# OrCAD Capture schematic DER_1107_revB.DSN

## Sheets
1 PAGE2: size B
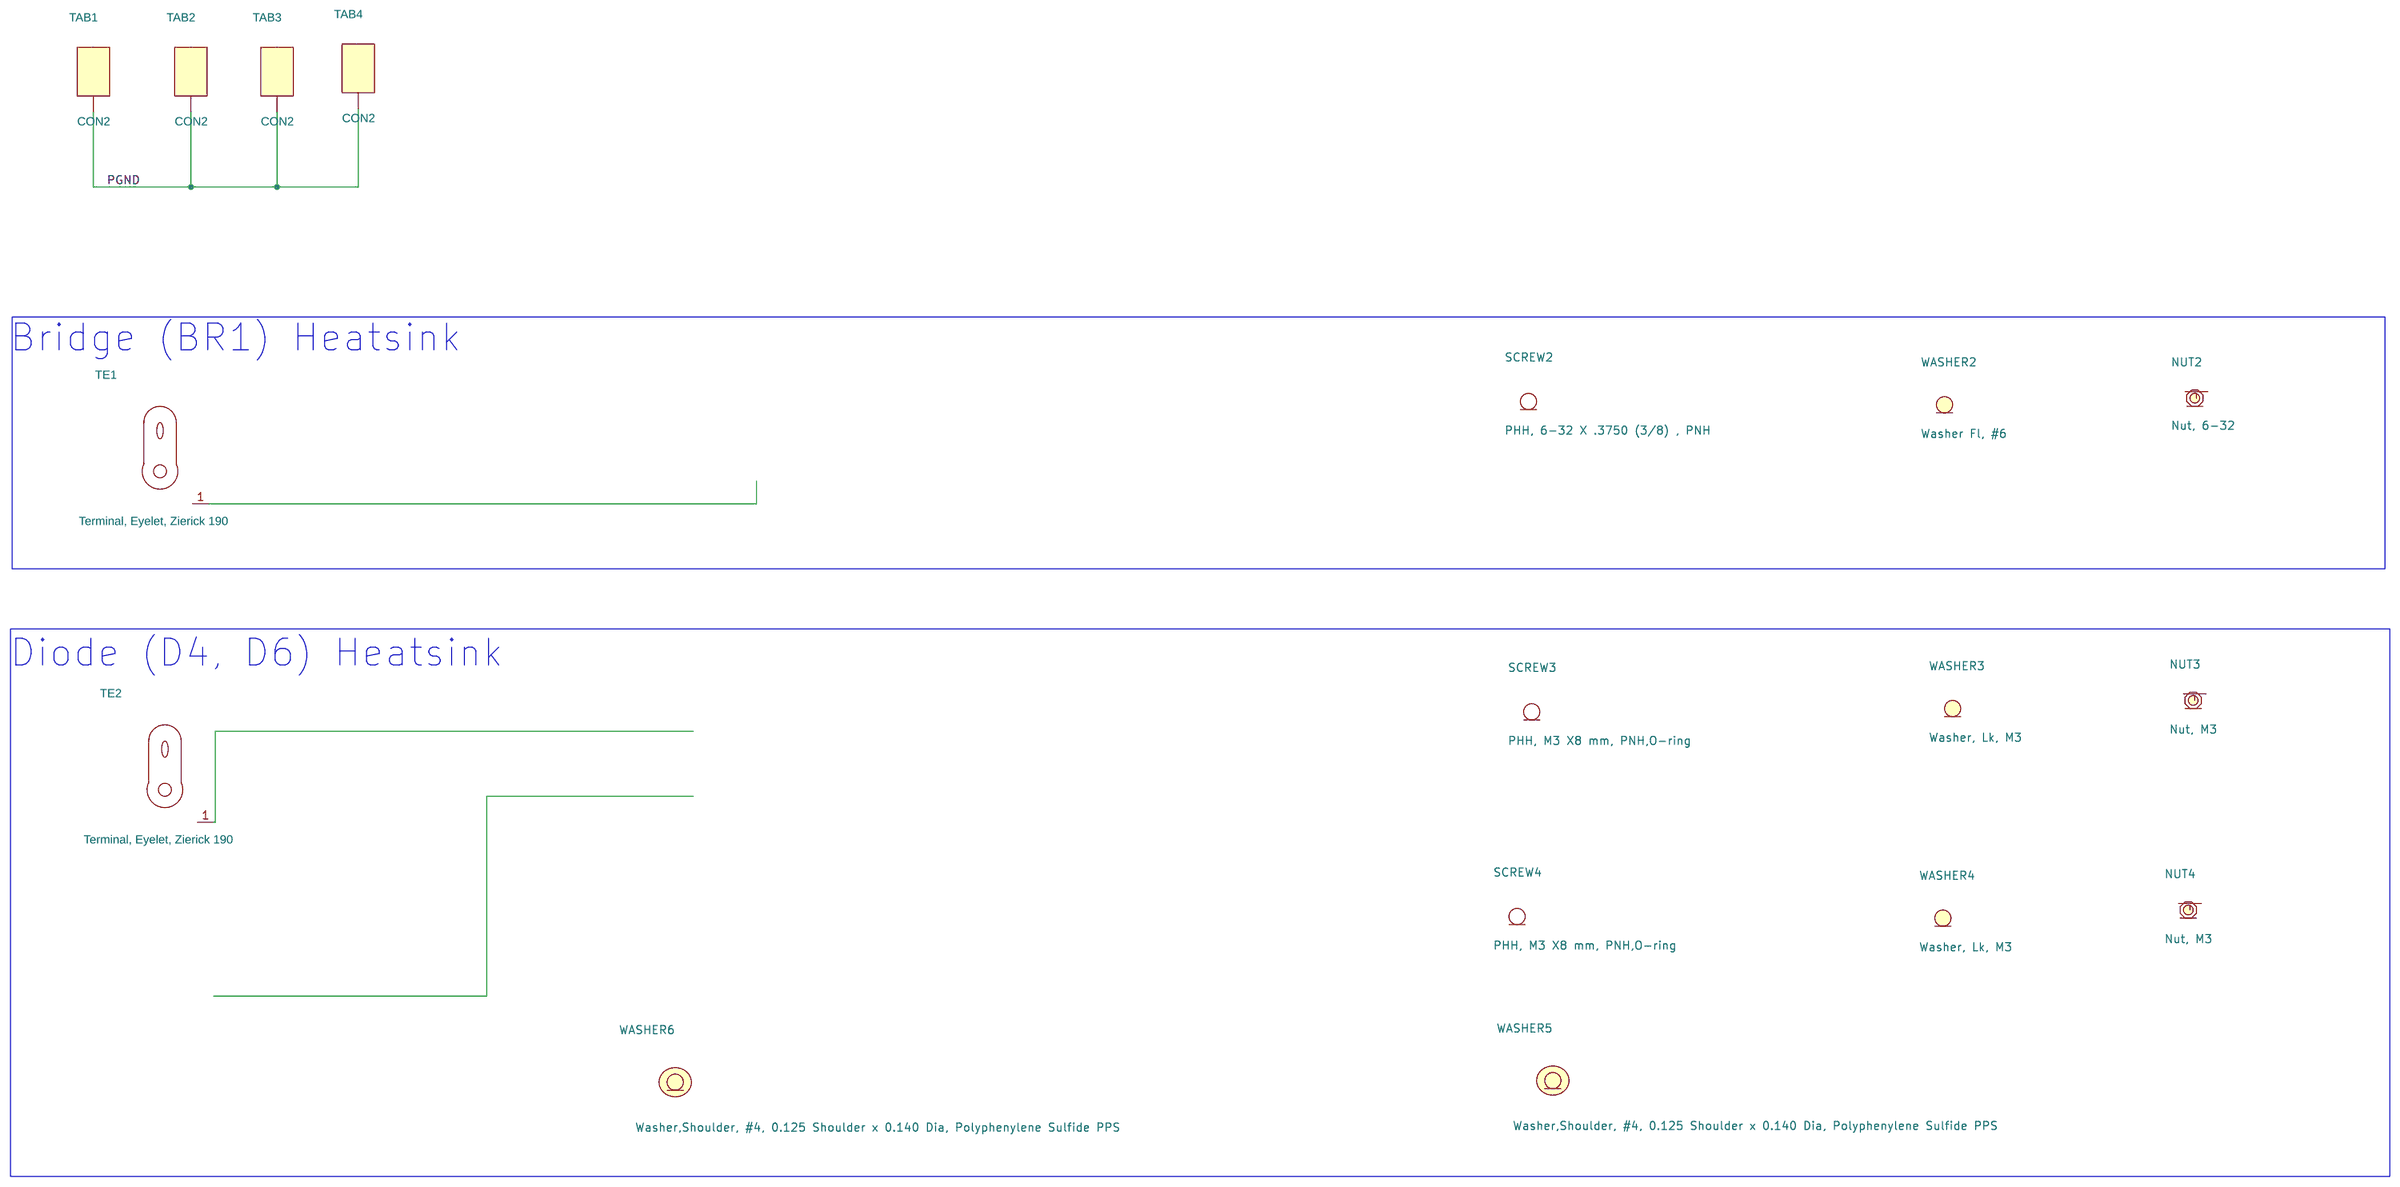
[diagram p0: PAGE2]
2 PAGE1: size C
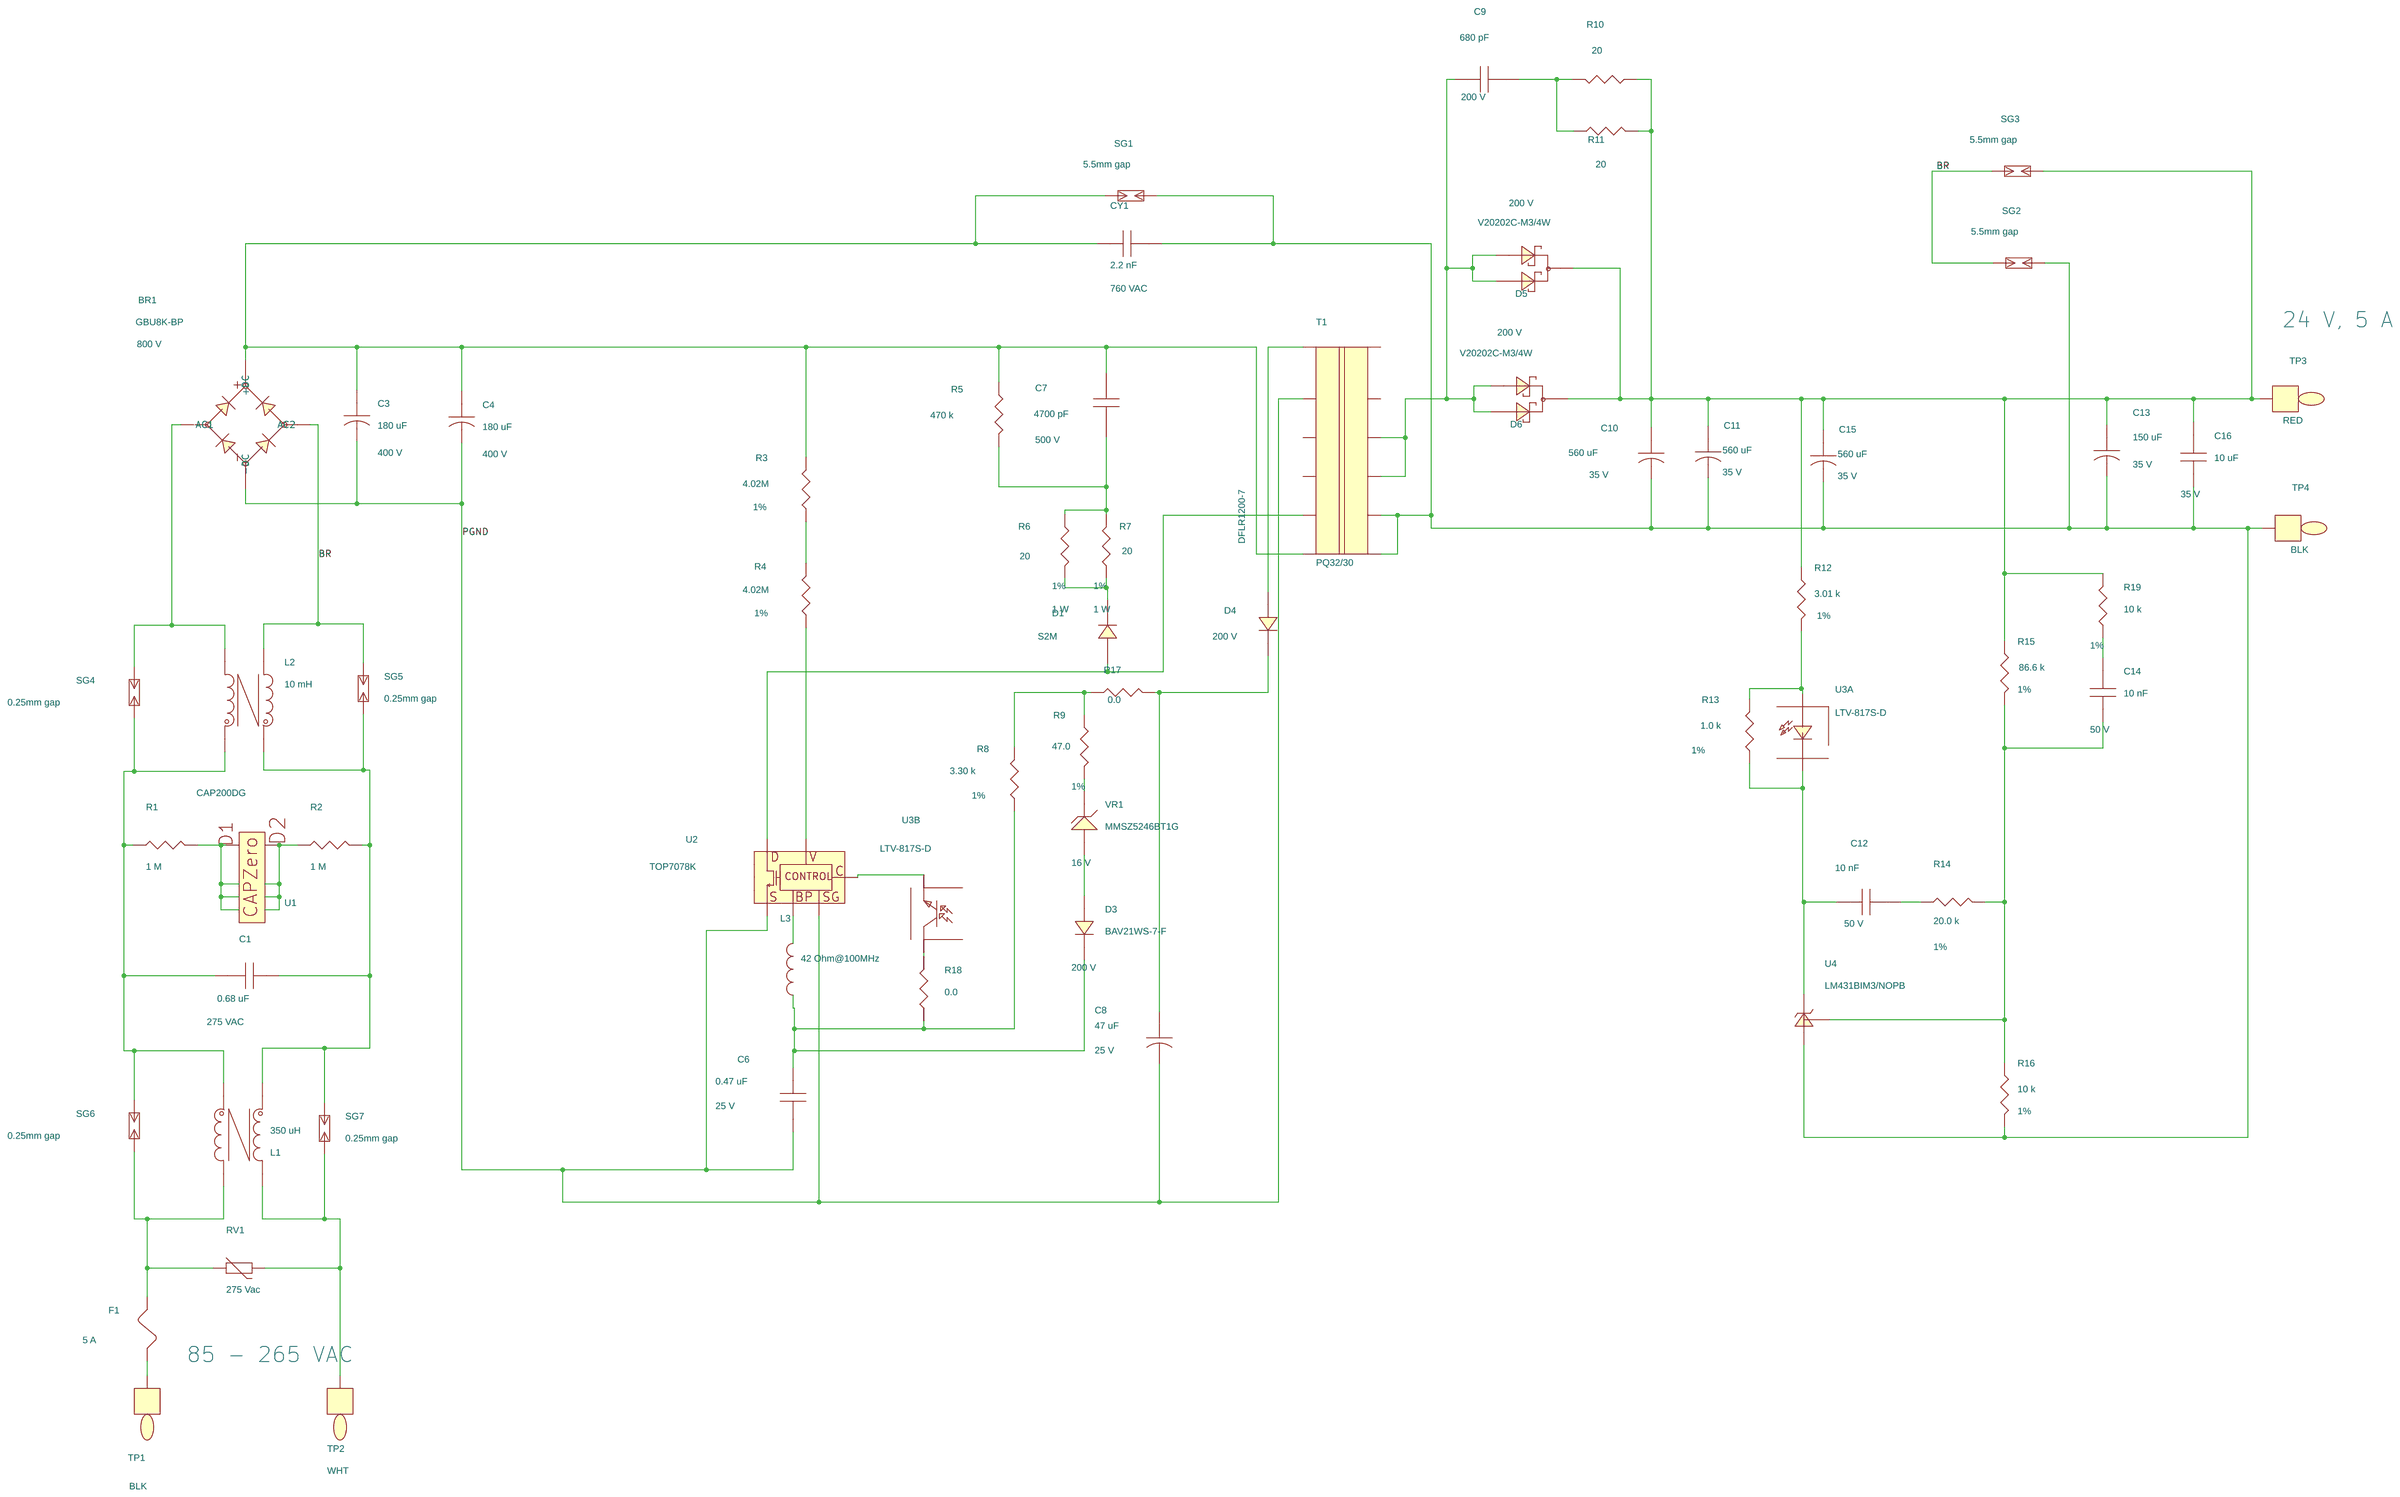
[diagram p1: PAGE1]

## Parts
sheet PAGE1
BR1  GBU8K-BP  [pidaxbridgegbu8]
C1  0.68 uF  [pi_npcap18x10x16p1D40]
C3  180 uF  [pipolcapclyd18mm040]
C4  180 uF  [pipolcapclyd18mm040]
C6  0.47 uF  [pismc0805]
C7  4700 pF  [pismc1206]
C8  47 uF  [pipolcapclyd200ls80030]
C9  680 pF  [pismc1206]
C10  560 uF  [pipolcapclyd10mm040]
C11  560 uF  [pipolcapclyd10mm040]
C12  10 nF  [pismc0805]
C13  150 uF  [pipolcapclyd320ls140030]
C14  10 nF  [pismc0805]
C15  560 uF  [pipolcapclyd10mm040]
C16  10 uF  [pismc1206]
CY1  2.2 nF  [pinpycaprad540x290ls400040]
D1  S2M  [pismsmb]
D3  BAV21WS-7-F  [pismsod323]
D4  DFLR1200-7  [pismddflr120012]
D5  V20202C-M3/4W  [pidvto2203vf1]
D6  V20202C-M3/4W  [pidvto2203vf1]
F1  5 A  [pi_rst_microfuse]
L1  350 uH  [piind4p_18p5x14p5mmd050]
L2  10 mH  [pi_toroid_balun_1]
L3  42 Ohm@100MHz  [INDC2012X105N]
R1  1 M  [pismr1206]
R2  1 M  [pismr1206]
R3  4.02M  [pismr1206]
R4  4.02M  [pismr1206]
R5  470 k  [pismr1206]
R6  20  [pismr2010]
R7  20  [pismr2010]
R8  3.30 k  [pismr0805]
R9  47.0  [pismr1206]
R10  20  [pismr2010]
R11  20  [pismr2010]
R12  3.01 k  [pismr1206]
R13  1.0 k  [pismr1206]
R14  20.0 k  [pismr1206]
R15  86.6 k  [pismr0805]
R16  10 k  [pismr1206]
R17  0.0  [pismr1206]
R18  0.0  [pismr1206]
R19  10 k  [pismr0805]
RV1  275 Vac  [pidisc350x160ls210x140040]
SG1  5.5mm gap  [PI_SPARK_GAP_5p5MM]
SG2  5.5mm gap  [PI_SPARK_GAP_5p5MM]
SG3  5.5mm gap  [PI_SPARK_GAP_5p5MM]
SG4  0.25mm gap  [PI_SPARK_GAP_0p25mm]
SG5  0.25mm gap  [PI_SPARK_GAP_0p25mm]
SG6  0.25mm gap  [PI_SPARK_GAP_0p25mm]
SG7  0.25mm gap  [PI_SPARK_GAP_0p25mm]
T1  PQ32/30  [pi_bbn_TDKbpq32_30_12p]
TP1  BLK  [pitpkeystone125x125]
TP2  WHT  [pitpkeystone125x125]
TP3  RED  [pitpkeystone125x125]
TP4  BLK  [pitpkeystone125x125]
U1  CAP200DG  [pi_ic_smd_so8_capzero]
U2  TOP7078K  [PI_eSOP-12B]
U3  LTV-817S-D  [pi_4_smd_gw_1]  (sections A,B)
U4  LM431BIM3/NOPB  [pismsot23123]
VR1  MMSZ5246BT1G  [PISM_SOD-123]
sheet PAGE2
NUT2  Nut, 6-32
NUT3  Nut, M3
NUT4  Nut, M3
SCREW2  PHH, 6-32 X .3750 (3/8) , PNH
SCREW3  PHH, M3 X8 mm, PNH,O-ring
SCREW4  PHH, M3 X8 mm, PNH,O-ring
TAB1  CON2  [pi_conn_qc_tab_2pin_ls200]
TAB2  CON2  [pi_conn_qc_tab_2pin_ls200]
TAB3  CON2  [pi_conn_qc_tab_2pin_ls200]
TAB4  CON2  [pi_conn_qc_tab_2pin_ls200]
TE1  Terminal, Eyelet, Zierick 190  [pi_zierick190_eyelet]
TE2  Terminal, Eyelet, Zierick 190  [pi_zierick190_eyelet]
WASHER2  Washer Fl, #6
WASHER3  Washer, Lk, M3
WASHER4  Washer, Lk, M3
WASHER5  Washer,Shoulder, #4, 0.125 Shoulder x 0.140 Dia, Polyphenylene Sulfide PPS
WASHER6  Washer,Shoulder, #4, 0.125 Shoulder x 0.140 Dia, Polyphenylene Sulfide PPS

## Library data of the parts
BR1 = DISCRETE_BRIDGE_+~~-: ALT_SYMBOLS: pidaxbridgegbu8_horz; Disp_Voltage: 800 V; FPLIST: pidaxbridgegbu8,pidaxbridgegbu8_horz; Part Number: 15-00347-00
C1 = CAP_NP: ALT_SYMBOLS: pi_npcap18x10x16p1D40H; Disp_Voltage: 275 VAC; FPLIST: pi_npcap18x10x16p1D40,pi_npcap18x10x16p1D40H; Part Number: 20-01496-00; ROOM: 1; Voltage: 275 VAC
C3 C4 = CAP_POL: ALT_SYMBOLS: pipolcapclyd18x40mm040; Disp_Voltage: 400 V; FPLIST: pipolcapclyd18mm040,pipolcapclyd18x40mm040; Part Number: 20-02404-00; Voltage: 400 V; Datasheet: \\PISHARE02\Application Design\PI_Parts\PI_Datasheets\Elect Cap\Nichicon_e-upz.pdf
C6 = CAP_NP: ALT_SYMBOLS: Unisem_RMCF0805UL; Disp_Voltage: 25 V; FPLIST: pismc0805,Unisem_RMCF0805UL; Part Number: 20-09182-00; Voltage: 25 V
C7 = CAP_NP: Disp_Voltage: 500 V; Part Number: 20-01417-00; Tol: 10; Voltage: 500 V
C8 = CAP_POL: ALT_SYMBOLS: pipolcapclyd200ls80030h; Disp_Voltage: 25 V; FPLIST: pipolcapclyd200ls80030,pipolcapclyd200ls80030h; Part Number: 20-00026-00; Tol: 20; Voltage: 25 V
C9 = CAP_NP: COMPGROUP: 2; Disp_Voltage: 200 V; Part Number: 20-02360-00; Tol: 10; Voltage: 200 V
C10 C11 C15 = CAP_POL: ALT_SYMBOLS: pipolcapcyld400ls2000401000h; Disp_Voltage: 35 V; FPLIST: pipolcapclyd10mm040,pipolcapcyld400ls2000401000h; PCB Editor PCBFP: pipolcapcyld400ls200040; Part Number: 20-00049-00; Voltage: 35 V
C12 C14 = CAP_NP: ALT_SYMBOLS: Unisem_RMCF0805UL; Disp_Voltage: 50 V; FPLIST: pismc0805,Unisem_RMCF0805UL; PCB Editor PCBFP: pinpcaprad200x100200030; Part Number: 20-09227-00; Voltage: 50 V
C13 = CAP_POL: ALT_SYMBOLS: pipolcapclyd320ls140030430h; Disp_Voltage: 35 V; FPLIST: pipolcapclyd320ls140030,pipolcapclyd320ls140030430h,pipolcapclyd320ls140030430h; Part Number: 20-00691-00; Tol: 20; Voltage: 35 V
C16 = CAP_NP: ALT_SYMBOLS: pismc1206_1; Disp_Voltage: 35 V; FPLIST: pismc1206,pismc1206_1; PCB Editor PCBFP: pinpcaprad200x100200030; Part Number: 20-01994-01; Voltage: 35 V
CY1 = CAP_NP: Disp_Voltage: 760 VAC; Part Number: 20-01427-00; Voltage: 760 VAC
D1 = DIODE: Disp_Voltage: 1000 V; Part Number: 15-02112-00
D3 = DIODE: ALT_SYMBOLS: SOD323_UL_IPC,pismsod323_1; Disp_Voltage: 200 V; FPLIST: pismsod323,SOD323_UL_IPC,pismsod323_1; Part Number: 15-00385-00
D4 = DIODE: Disp_Voltage: 200 V; Part Number: 15-01019-00
D5 D6 = DS_DUAL_CK_AKA: ALT_SYMBOLS: pidvto2203,pidvto2203h; Disp_Voltage: 200 V; FPLIST: pidvto2203vf1,pidvto2203,pidvto2203h; Part Number: 15-02210-00
F1 = FUSE: ALT_SYMBOLS: pirstmicrofusehoz; COMPGROUP: 1; FPLIST: pi_rst_microfuse,pirstmicrofusehoz; Part Number: 40-00052-00; ROOM: 1
L1 = CMC__4P_14_23: Part Number: 30-00675-00
L2 = TORRID_4P_12_34: Part Number: 32-00016-00
L3 = INDUCTOR_BEAD: Part Number: 30-00656-00
R1 R2 = R: Part Number: 05-01424-00
R3 R4 = R: ALT_SYMBOLS: pismr1206_1; Disp_Power: 0.25 W; Disp_Tol: 1%; FPLIST: pismr1206,pismr1206_1; Part Number: 05-06470-00
R5 = R: Part Number: 05-01416-00
R6 R7 = R: Disp_Power: 1 W; Disp_Tol: 1%; Part Number: 05-06494-00
R8 = R: ALT_SYMBOLS: Unisem_RMCF0805UL; Disp_Tol: 1%; FPLIST: pismr0805,Unisem_RMCF0805UL; Part Number: 05-05369-00
R9 = R: Disp_Tol: 1%; Part Number: 05-03475-00
R10 R11 = R: Disp_Power: 1 W; Disp_Tol: 1%; PCB Editor PCBFP: pi14wvresd100ls100d030,pi14wvresd100ls200d030,pi14wresd100ls400d030,pi14wresd100ls500d030; Part Number: 05-06494-00
R12 = R: Disp_Tol: 1%; PCB Editor PCBFP: pi14wvresd100ls100d030,pi14wvresd100ls200d030,pi14wresd100ls400d030,pi14wresd100ls500d030; Part Number: 05-00239-00
R13 = R: Disp_Tol: 1%; PCB Editor PCBFP: pi14wvresd100ls100d030,pi14wvresd100ls200d030,pi14wresd100ls400d030,pi14wresd100ls500d030; Part Number: 05-00193-00
R14 = R: Disp_Tol: 1%; Part Number: 05-00318-00
R15 = R: ALT_SYMBOLS: Unisem_RMCF0805UL; Disp_Tol: 1%; FPLIST: pismr0805,Unisem_RMCF0805UL; PCB Editor PCBFP: pi14wvresd100ls100d030,pi14wvresd100ls200d030,pi14wresd100ls400d030,pi14wresd100ls500d030; Part Number: 05-00774-00
R16 = R: Disp_Tol: 1%; PCB Editor PCBFP: pi14wvresd100ls100d030,pi14wvresd100ls200d030,pi14wresd100ls400d030,pi14wresd100ls500d030; Part Number: 05-06571-00
R17 R18 = R: Part Number: 05-03160-00
R19 = R: ALT_SYMBOLS: Unisem_RMCF0805UL; Disp_Tol: 1%; FPLIST: pismr0805,Unisem_RMCF0805UL; Part Number: 05-00684-00
RV1 = VARISTOR: ALT_SYMBOLS: pi_disc_354x220_ls220x10_040_h; FPLIST: pidisc350x160ls210x140040,pi_disc_354x220_ls220x10_040_h; Part Number: 85-00015-00; ROOM: 1
SG1-SG3 = SPARK_GAP: Part Number: 66-00357-00
SG4-SG7 = SPARK_GAP: Part Number: 66-00360-00
T1 = BPQ32_30_12P_GENERIC: Part Number: 25-01198-00
TP1 TP4 = TESTPOINT: ALT_SYMBOLS: TP_5010-14; Part Number: 35-00042-00
TP2 = TESTPOINT: ALT_SYMBOLS: TP_5010-14; Part Number: 35-00044-00
TP3 = TESTPOINT: ALT_SYMBOLS: TP_5010-14; Part Number: 35-00043-00
U1 = CAPZero: Part Number: 10-00958-00; ROOM: 1
U2 = TOPSwitch-GaN_eSOP12B: Part Number: 10-01636-00
U3 = OPTO_A_B: ALT_SYMBOLS: pi_4_smd_gw; FPLIST: pi_4_smd_gw_1,pi_4_smd_gw; Part Number: 53-00063-00; COMPGROUP: 2
U4 = TL431_SOT-23_CAR: Part Number: 45-00232-00
VR1 = DIODE_ZENER: Disp_Voltage: 16 V; Part Number: 15-02019-00
NUT2 = NUT_HEX_6-32: Part Number: 75-00025-00
NUT3 NUT4 = NUT_HEX_M3: Part Number: 75-00055-00
SCREW2 = SCR_6-32: Part Number: 75-00009-00
SCREW3 SCREW4 = SCR_M3: Part Number: 75-00215-00
TAB1-TAB4 = CON1_2P_TAB: Part Number: 35-00281-00
TE1 TE2 = TERM_EYLT: Part Number: 60-00016-00
WASHER2 = WASH_FLAT_6: Part Number: 75-00033-00
WASHER3 WASHER4 = WASH_LOCK_M3: Part Number: 75-00059-00
WASHER5 WASHER6 = WASH_SHLDR_4: Part Number: 75-00154-00

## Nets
PGND: BR1.4(-DC) C3.2 C4.2 C6.2 C8.2 T1.2 U2.4 U2.7
PGND (page PAGE2): TAB1.1 TAB2.1 TAB3.1 TAB4.1
BR: BR1.3(AC2) L2.4 SG2.1 SG3.1 SG5.2
N1180572: C9.1 D5.1(A1) D5.3(A2) D6.1(A1) D6.3(A2) T1.9 T1.10
N1180580: C9.2 R10.2 R11.2
N1180640: BR1.1(+DC) C3.1 C4.1 C7.1 CY1.1 R3.1 R5.1 SG1.1 T1.6
N1180772: C10.1 C11.1 C13.1 C15.1 C16.2 D5.2(CATHODE) D6.2(CATHODE) R10.1 R11.1 R12.1 R15.1 R19.1 SG3.2 TP3.1
N1181018: C10.2 C11.2 C13.2 C15.2 C16.1 CY1.2 R16.2 SG1.2 SG2.2 T1.7 T1.8 TP4.1 U4.2(A)
N1181144: R3.2 R4.1
N1181148: D1.2 T1.5 U2.6
N1181266: C8.1 D4.1 R17.2
N1181270: R12.2 R13.1 U3.1(A)
N1181336: C14.1 R14.1 R15.2 R16.1 U4.3(VREF)
N1181354: R4.2 U2.1
N1181442: C12.1 R13.2 U3.2(C) U4.1(C)
N1193924: D3.2 VR1.2
N1193928: R9.2 VR1.1
N11509583: C1.2 L1.2 L2.1 R1.1 SG4.1 SG6.2
N11509663: R1.2 U1.1(NC1) U1.2(D1) U1.3(NC2) U1.4(NC3)
N11509667: R2.1 U1.5(NC4) U1.6(NC5) U1.7(D2) U1.8(NC8)
N11509705: C1.1 L1.1 L2.3 R2.2 SG5.1 SG7.2
N11509765: F1.2 L1.3 RV1.1 SG6.1
N11509809: L1.4 RV1.2 SG7.1 TP2.1
N11511065: BR1.2(AC1) L2.2 SG4.2
N11514098: C12.2 R14.2
N11565135: C7.2 R5.2 R6.1 R7.1
N11566250: F1.1 TP1.1
N11596495: D1.1 R6.2 R7.2
N12575460: R8.1 R9.1 R17.1
N12576026: C6.1 D3.1 L3.1 R8.2 R18.1
N12646059: L3.2 U2.2
N12657145: R18.2 U3.4(C)
N12660745: D4.2 T1.1
N12661914: U2.3 U3.3(E)
N12671781: C14.2 R19.2

Not connected (* = marked no-connect by the designer): T1 3 4 11 12; TAB1 2; TAB2 2; TAB3 2; TAB4 2; TE1 1; TE2 1; U2 8 9 10 11 12 13

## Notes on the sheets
sheet 1
- Bridge (BR1) Heatsink
- Diode (D4, D6) Heatsink
sheet 2
- 24 V, 5 A
- 85 - 265 VAC
